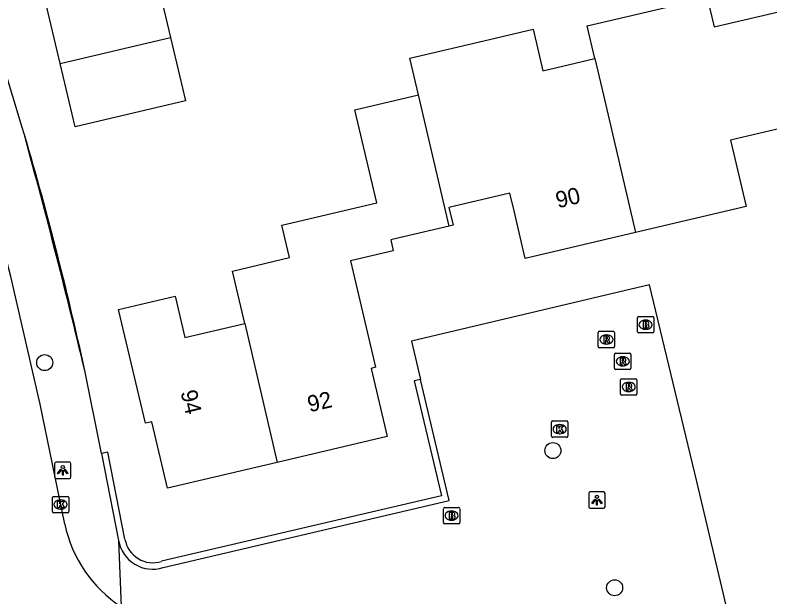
# Model space of a CAD drawing. Extents: x 157663 to 158496, y 379212 to 380934.
# Drawn here: x 158281.55 to 158327.67, y 380607.68 to 380643.22 of the extents above; entities that cross this region are included whole.
import ezdxf

# ---------------------------------------------------------------- set-up
doc = ezdxf.new("R2010")
doc.units = 0
for name, color, linetype in [('IMGEO_Boom', 7, 'Continuous'), ('IMGEO_Brandkraan', 7, 'Continuous'), ('IMGEO_Haag', 7, 'Continuous'), ('IMGEO_Hek', 7, 'Continuous'), ('IMGEO_Kolk', 7, 'Continuous'), ('IMGEO_Lichtpunt', 7, 'Continuous'), ('IMGEO_Pand', 7, 'Continuous'), ('IMGEO_Pand_nummerreeks', 7, 'Continuous'), ('IMGEO_Rijbaan_lokaal_open', 7, 'Continuous'), ('IMGEO_Rioolput', 7, 'Continuous'), ('IMGEO_Voetpad_open', 7, 'Continuous')]:
    doc.layers.add(name, color=color, linetype=linetype)

msp = doc.modelspace()

# ---------------------------------------------------------------- linework, layer by layer
at = {"layer": 'IMGEO_Boom'}
for centre in [(158283.36, 380621.994), (158314.409, 380616.619), (158318.184, 380608.243)]:
    msp.add_circle(centre, 0.489, dxfattribs=at)
at = {"layer": 'IMGEO_Brandkraan'}
for p, q in [((158319.57, 380623.885), (158319.57, 380624.737)), ((158319.645, 380624.811), (158320.497, 380624.811)), ((158320.058, 380624.591), (158320.083, 380624.591)), ((158320.571, 380624.737), (158320.571, 380623.885)), ((158320.081, 380624.031), (158320.056, 380624.031)), ((158320.497, 380623.811), (158319.645, 380623.811)), ((158307.721, 380612.222), (158307.721, 380613.074)), ((158307.796, 380613.148), (158308.648, 380613.148)), ((158308.209, 380612.928), (158308.234, 380612.928)), ((158308.722, 380613.074), (158308.722, 380612.222)), ((158308.648, 380612.148), (158307.796, 380612.148)), ((158308.232, 380612.368), (158308.207, 380612.368))]:
    msp.add_line(p, q, dxfattribs=at)
for points in [[(158319.57, 380623.885), (158319.57, 380624.737)], [(158319.645, 380624.811), (158320.497, 380624.811)], [(158319.918, 380624.511), (158319.918, 380624.111), (158320.131, 380624.111)], [(158320.149, 380624.511), (158319.918, 380624.511)], [(158320.097, 380624.43), (158320.043, 380624.43), (158320.043, 380624.354)], [(158320.571, 380624.737), (158320.571, 380623.885)], [(158320.043, 380624.354), (158320.096, 380624.354)], [(158320.105, 380624.278), (158320.043, 380624.278), (158320.043, 380624.197)], [(158320.043, 380624.197), (158320.105, 380624.197)], [(158320.497, 380623.811), (158319.645, 380623.811)], [(158307.721, 380612.222), (158307.721, 380613.074)], [(158307.796, 380613.148), (158308.648, 380613.148)], [(158308.722, 380613.074), (158308.722, 380612.222)], [(158308.069, 380612.848), (158308.069, 380612.448), (158308.282, 380612.448)], [(158308.3, 380612.848), (158308.069, 380612.848)], [(158308.248, 380612.767), (158308.194, 380612.767), (158308.194, 380612.691)], [(158308.194, 380612.691), (158308.247, 380612.691)], [(158308.256, 380612.615), (158308.194, 380612.615), (158308.194, 380612.534)], [(158308.194, 380612.534), (158308.256, 380612.534)], [(158308.648, 380612.148), (158307.796, 380612.148)]]:
    msp.add_lwpolyline(points, dxfattribs=at)
for centre, radius, start, end in [((158319.647, 380624.735), 0.0765, 91.552, 178.448), ((158319.647, 380624.735), 0.0765, 91.552, 178.448), ((158320.098, 380624.392), 0.0379, 267.8285, 90.9355), ((158320.153, 380624.366), 0.145, 59.4692, 91.5367), ((158320.178, 380624.413), 0.0922, 285.5137, 58.1501), ((158320.495, 380624.735), 0.0765, 1.552, 88.448), ((158320.495, 380624.735), 0.0765, 1.552, 88.448), ((158320.106, 380624.237), 0.0404, 269.8759, 90.5077), ((158320.137, 380624.362), 0.251, 268.6676, 293.5347), ((158320.183, 380624.221), 0.105, 301.3115, 78.989), ((158319.647, 380623.887), 0.0765, 181.552, 268.448), ((158319.647, 380623.887), 0.0765, 181.552, 268.448), ((158320.495, 380623.887), 0.0765, 271.552, 358.448), ((158320.495, 380623.887), 0.0765, 271.552, 358.448), ((158307.798, 380613.072), 0.0765, 91.552, 178.448), ((158307.798, 380613.072), 0.0765, 91.552, 178.448), ((158308.646, 380613.072), 0.0765, 1.552, 88.448), ((158308.646, 380613.072), 0.0765, 1.552, 88.448), ((158308.249, 380612.729), 0.0379, 267.8285, 90.9355), ((158308.257, 380612.574), 0.0404, 269.8759, 90.5077), ((158308.288, 380612.699), 0.251, 268.6676, 293.5347), ((158308.304, 380612.703), 0.145, 59.4692, 91.5367), ((158308.329, 380612.75), 0.0922, 285.5137, 58.1501), ((158308.334, 380612.558), 0.105, 301.3115, 78.989), ((158307.798, 380612.224), 0.0765, 181.552, 268.448), ((158307.798, 380612.224), 0.0765, 181.552, 268.448), ((158308.646, 380612.224), 0.0765, 271.552, 358.448), ((158308.646, 380612.224), 0.0765, 271.552, 358.448)]:
    msp.add_arc(centre, radius, start, end, dxfattribs=at)
for centre, major_axis, ratio, start_param, end_param in [((158320.057, 380624.311), (-0.387, 0.002), 0.722429, 4.712389, 7.853982), ((158320.082, 380624.311), (-0.39, 0.002), 0.717154, 1.570796, 4.712389), ((158308.208, 380612.648), (-0.387, 0.002), 0.722429, 4.712389, 7.853982), ((158308.233, 380612.648), (-0.39, 0.002), 0.717154, 1.570796, 4.712389)]:
    msp.add_ellipse(centre, major_axis=major_axis, ratio=ratio, start_param=start_param, end_param=end_param, dxfattribs=at)
at = {"layer": 'IMGEO_Haag'}
for points in [[(158306.328, 380620.973), (158305.939, 380620.881), (158307.597, 380613.868), (158290.496, 380609.857)], [(158288.265, 380611.201), (158287.219, 380616.53), (158286.826, 380616.453)]]:
    msp.add_lwpolyline(points, dxfattribs=at)
msp.add_arc((158289.966, 380611.5), 1.727, 189.9838, 287.885, dxfattribs=at)
at = {"layer": 'IMGEO_Hek'}
msp.add_arc((157862.374, 380520.498), 435.318, 13.41743, 15.43611, dxfattribs=at)
at = {"layer": 'IMGEO_Kolk'}
for p, q in [((158314.398, 380618.432), (158315.25, 380618.432)), ((158314.323, 380617.506), (158314.323, 380618.358)), ((158314.811, 380618.212), (158314.836, 380618.212)), ((158315.324, 380618.358), (158315.324, 380617.506)), ((158314.834, 380617.652), (158314.809, 380617.652)), ((158315.25, 380617.432), (158314.398, 380617.432)), ((158283.903, 380613.824), (158284.755, 380613.824)), ((158283.828, 380612.898), (158283.828, 380613.75)), ((158284.316, 380613.604), (158284.341, 380613.604)), ((158284.829, 380613.75), (158284.829, 380612.898)), ((158284.339, 380613.044), (158284.314, 380613.044)), ((158284.755, 380612.824), (158283.903, 380612.824))]:
    msp.add_line(p, q, dxfattribs=at)
for points in [[(158314.398, 380618.432), (158315.25, 380618.432)], [(158314.323, 380617.506), (158314.323, 380618.358)], [(158314.644, 380618.132), (158314.767, 380618.132), (158314.767, 380617.981), (158314.897, 380618.132), (158315.061, 380618.132), (158314.915, 380617.981), (158315.068, 380617.732), (158314.916, 380617.732), (158314.831, 380617.896), (158314.767, 380617.829), (158314.767, 380617.732), (158314.644, 380617.732), (158314.644, 380618.132)], [(158315.324, 380618.358), (158315.324, 380617.506)], [(158315.25, 380617.432), (158314.398, 380617.432)], [(158283.903, 380613.824), (158284.755, 380613.824)], [(158283.828, 380612.898), (158283.828, 380613.75)], [(158284.149, 380613.524), (158284.272, 380613.524), (158284.272, 380613.373), (158284.402, 380613.524), (158284.566, 380613.524), (158284.42, 380613.373), (158284.573, 380613.124), (158284.421, 380613.124), (158284.336, 380613.288), (158284.272, 380613.221), (158284.272, 380613.124), (158284.149, 380613.124), (158284.149, 380613.524)], [(158284.829, 380613.75), (158284.829, 380612.898)], [(158284.755, 380612.824), (158283.903, 380612.824)]]:
    msp.add_lwpolyline(points, dxfattribs=at)
for centre, start, end in [((158314.4, 380618.356), 91.552, 178.448), ((158314.4, 380618.356), 91.552, 178.448), ((158315.248, 380618.356), 1.552, 88.448), ((158315.248, 380618.356), 1.552, 88.448), ((158314.4, 380617.508), 181.552, 268.448), ((158314.4, 380617.508), 181.552, 268.448), ((158315.248, 380617.508), 271.552, 358.448), ((158315.248, 380617.508), 271.552, 358.448), ((158283.905, 380613.748), 91.552, 178.448), ((158283.905, 380613.748), 91.552, 178.448), ((158284.753, 380613.748), 1.552, 88.448), ((158284.753, 380613.748), 1.552, 88.448), ((158283.905, 380612.9), 181.552, 268.448), ((158283.905, 380612.9), 181.552, 268.448), ((158284.753, 380612.9), 271.552, 358.448), ((158284.753, 380612.9), 271.552, 358.448)]:
    msp.add_arc(centre, 0.0765, start, end, dxfattribs=at)
for centre, major_axis, ratio, start_param, end_param in [((158314.81, 380617.932), (-0.387, 0.002), 0.722429, 4.712389, 7.853982), ((158314.835, 380617.932), (-0.39, 0.002), 0.717154, 1.570796, 4.712389), ((158284.315, 380613.324), (-0.387, 0.002), 0.722429, 4.712389, 7.853982), ((158284.34, 380613.324), (-0.39, 0.002), 0.717154, 1.570796, 4.712389)]:
    msp.add_ellipse(centre, major_axis=major_axis, ratio=ratio, start_param=start_param, end_param=end_param, dxfattribs=at)
at = {"layer": 'IMGEO_Lichtpunt'}
for p, q in [((158283.965, 380615.82), (158283.965, 380615.013)), ((158283.965, 380615.82), (158283.965, 380615.013)), ((158284.867, 380615.915), (158284.059, 380615.915)), ((158284.867, 380615.915), (158284.059, 380615.915)), ((158284.961, 380615.013), (158284.961, 380615.82)), ((158284.961, 380615.013), (158284.961, 380615.82)), ((158284.059, 380614.919), (158284.867, 380614.919)), ((158284.059, 380614.919), (158284.867, 380614.919)), ((158316.601, 380613.999), (158316.601, 380613.192)), ((158316.601, 380613.999), (158316.601, 380613.192)), ((158317.503, 380614.094), (158316.695, 380614.094)), ((158317.503, 380614.094), (158316.695, 380614.094)), ((158317.597, 380613.192), (158317.597, 380613.999)), ((158317.597, 380613.192), (158317.597, 380613.999)), ((158316.695, 380613.098), (158317.503, 380613.098)), ((158316.695, 380613.098), (158317.503, 380613.098))]:
    msp.add_line(p, q, dxfattribs=at)
for points in [[(158284.339, 380615.484), (158284.378, 380615.456), (158284.19, 380615.194), (158284.152, 380615.221), (158284.339, 380615.484)], [(158284.441, 380615.436), (158284.488, 380615.436), (158284.488, 380615.114), (158284.441, 380615.114), (158284.441, 380615.436)], [(158284.551, 380615.456), (158284.589, 380615.483), (158284.776, 380615.221), (158284.737, 380615.193), (158284.551, 380615.456)], [(158316.975, 380613.663), (158317.014, 380613.635), (158316.826, 380613.373), (158316.788, 380613.4), (158316.975, 380613.663)], [(158317.077, 380613.615), (158317.124, 380613.615), (158317.124, 380613.293), (158317.077, 380613.293), (158317.077, 380613.615)], [(158317.187, 380613.635), (158317.225, 380613.662), (158317.412, 380613.4), (158317.373, 380613.372), (158317.187, 380613.635)]]:
    msp.add_lwpolyline(points, dxfattribs=at)
for centre in [(158284.464, 380615.618), (158317.1, 380613.797)]:
    msp.add_circle(centre, 0.0994, dxfattribs=at)
for centre, start, end in [((158284.059, 380615.82), 90, 180), ((158284.059, 380615.82), 90, 180), ((158284.867, 380615.82), 0, 90), ((158284.867, 380615.82), 0, 90), ((158284.059, 380615.013), 180, 270), ((158284.059, 380615.013), 180, 270), ((158284.867, 380615.013), 270, 0), ((158284.867, 380615.013), 270, 360), ((158316.695, 380613.999), 90, 180), ((158316.695, 380613.999), 90, 180), ((158317.503, 380613.999), 0, 90), ((158317.503, 380613.999), 0, 90), ((158316.695, 380613.192), 180, 270), ((158316.695, 380613.192), 180, 270), ((158317.503, 380613.192), 270, 0), ((158317.503, 380613.192), 270, 360)]:
    msp.add_arc(centre, 0.0946, start, end, dxfattribs=at)
at = {"layer": 'IMGEO_Pand'}
for points in [[(158284.305, 380640.265), (158283.395, 380644.136), (158290.137, 380645.719), (158291.046, 380641.85)], [(158316.97, 380640.574), (158316.5, 380642.576), (158323.841, 380644.3), (158324.263, 380642.505), (158334.831, 380644.988), (158338.49, 380629.41)], [(158306.193, 380638.357), (158305.669, 380640.588), (158310.537, 380641.732), (158313.202, 380642.358), (158313.796, 380639.828), (158316.97, 380640.574)], [(158291.046, 380641.85), (158291.955, 380637.978), (158285.214, 380636.395), (158284.305, 380640.265)], [(158284.305, 380640.265), (158291.046, 380641.85)], [(158316.97, 380640.574), (158317.497, 380638.329), (158319.465, 380629.95)], [(158295.578, 380624.388), (158294.826, 380627.586), (158298.321, 380628.407), (158297.854, 380630.395), (158303.656, 380631.758), (158302.319, 380637.447), (158306.193, 380638.357)], [(158308.08, 380630.334), (158306.193, 380638.357)], [(158331.691, 380627.813), (158330.427, 380627.557), (158330.324, 380627.996), (158331.494, 380628.271), (158330.679, 380631.736), (158329.509, 380631.465), (158328.37, 380636.312), (158325.265, 380635.583), (158326.215, 380631.535), (158319.465, 380629.95)], [(158319.465, 380629.95), (158312.717, 380628.365), (158312.036, 380631.263), (158311.78, 380632.354), (158308.06, 380631.481), (158308.316, 380630.389), (158308.08, 380630.334)], [(158308.08, 380630.334), (158305.278, 380629.676), (158304.499, 380629.493), (158304.658, 380628.818), (158302.051, 380628.206), (158303.577, 380621.71), (158303.307, 380621.646), (158304.286, 380617.478), (158297.573, 380615.901)], [(158297.573, 380615.901), (158290.858, 380614.324), (158289.904, 380618.383), (158289.518, 380618.292), (158287.878, 380625.235), (158291.329, 380626.045), (158291.92, 380623.529), (158295.578, 380624.388)], [(158295.578, 380624.388), (158297.573, 380615.901)]]:
    msp.add_lwpolyline(points, dxfattribs=at)
at = {"layer": 'IMGEO_Rijbaan_lokaal_open'}
msp.add_lwpolyline([(158284.585, 380612.128), (158283.092, 380619.448), (158281.301, 380627.252), (158279.102, 380635.44), (158277.35, 380641.254), (158275.628, 380646.459), (158269.134, 380664.006), (158269.099, 380664.106)], dxfattribs=at)
msp.add_arc((158292.409, 380613.78), 7.996, 191.92, 236.8741, dxfattribs=at)
at = {"layer": 'IMGEO_Rioolput'}
for p, q in [((158317.181, 380622.981), (158317.181, 380623.833)), ((158317.256, 380623.907), (158318.108, 380623.907)), ((158317.669, 380623.687), (158317.694, 380623.687)), ((158318.182, 380623.833), (158318.182, 380622.981)), ((158317.692, 380623.127), (158317.667, 380623.127)), ((158318.108, 380622.907), (158317.256, 380622.907)), ((158318.255, 380622.575), (158319.107, 380622.575)), ((158318.18, 380621.649), (158318.18, 380622.501)), ((158318.668, 380622.355), (158318.693, 380622.355)), ((158319.181, 380622.501), (158319.181, 380621.649)), ((158318.691, 380621.795), (158318.666, 380621.795)), ((158319.107, 380621.575), (158318.255, 380621.575)), ((158318.543, 380620.085), (158318.543, 380620.937)), ((158318.618, 380621.011), (158319.47, 380621.011)), ((158319.031, 380620.791), (158319.056, 380620.791)), ((158319.544, 380620.937), (158319.544, 380620.085)), ((158319.47, 380620.011), (158318.618, 380620.011)), ((158319.054, 380620.231), (158319.029, 380620.231))]:
    msp.add_line(p, q, dxfattribs=at)
for points in [[(158317.181, 380622.981), (158317.181, 380623.833)], [(158317.256, 380623.907), (158318.108, 380623.907)], [(158317.77, 380623.605), (158317.518, 380623.607), (158317.518, 380623.207)], [(158317.696, 380623.526), (158317.642, 380623.526), (158317.642, 380623.445)], [(158318.182, 380623.833), (158318.182, 380622.981)], [(158317.518, 380623.207), (158317.642, 380623.207), (158317.642, 380623.369), (158317.653, 380623.369)], [(158317.642, 380623.445), (158317.694, 380623.445)], [(158317.7, 380623.34), (158317.771, 380623.207), (158317.911, 380623.207), (158317.846, 380623.333)], [(158318.108, 380622.907), (158317.256, 380622.907)], [(158318.255, 380622.575), (158319.107, 380622.575)], [(158318.18, 380621.649), (158318.18, 380622.501)], [(158318.769, 380622.273), (158318.517, 380622.275), (158318.517, 380621.875)], [(158318.695, 380622.194), (158318.641, 380622.194), (158318.641, 380622.113)], [(158318.641, 380622.113), (158318.693, 380622.113)], [(158319.181, 380622.501), (158319.181, 380621.649)], [(158318.517, 380621.875), (158318.641, 380621.875), (158318.641, 380622.037), (158318.652, 380622.037)], [(158318.699, 380622.008), (158318.77, 380621.875), (158318.91, 380621.875), (158318.845, 380622.001)], [(158319.107, 380621.575), (158318.255, 380621.575)], [(158318.543, 380620.085), (158318.543, 380620.937)], [(158318.618, 380621.011), (158319.47, 380621.011)], [(158319.544, 380620.937), (158319.544, 380620.085)], [(158319.132, 380620.709), (158318.88, 380620.711), (158318.88, 380620.311)], [(158318.88, 380620.311), (158319.004, 380620.311), (158319.004, 380620.473), (158319.015, 380620.473)], [(158319.058, 380620.63), (158319.004, 380620.63), (158319.004, 380620.549)], [(158319.004, 380620.549), (158319.056, 380620.549)], [(158319.062, 380620.444), (158319.133, 380620.311), (158319.273, 380620.311), (158319.208, 380620.437)], [(158319.47, 380620.011), (158318.618, 380620.011)]]:
    msp.add_lwpolyline(points, dxfattribs=at)
for centre, radius, start, end in [((158317.258, 380623.831), 0.0765, 91.552, 178.448), ((158317.258, 380623.831), 0.0765, 91.552, 178.448), ((158317.702, 380623.43), 0.0964, 77.0061, 93.1865), ((158317.716, 380623.487), 0.0378, 276.6634, 79.6772), ((158317.769, 380623.495), 0.109, 350.3612, 89.416), ((158318.106, 380623.831), 0.0765, 1.552, 88.448), ((158318.106, 380623.831), 0.0765, 1.552, 88.448), ((158317.652, 380623.316), 0.0533, 26.0293, 88.6989), ((158317.678, 380623.634), 0.19, 274.7715, 282.9687), ((158317.767, 380623.495), 0.112, 277.5842, 350.9817), ((158317.751, 380623.28), 0.108, 29.5134, 73.7905), ((158317.258, 380622.983), 0.0765, 181.552, 268.448), ((158317.258, 380622.983), 0.0765, 181.552, 268.448), ((158318.106, 380622.983), 0.0765, 271.552, 358.448), ((158318.106, 380622.983), 0.0765, 271.552, 358.448), ((158318.257, 380622.499), 0.0765, 91.552, 178.448), ((158318.257, 380622.499), 0.0765, 91.552, 178.448), ((158319.105, 380622.499), 0.0765, 1.552, 88.448), ((158319.105, 380622.499), 0.0765, 1.552, 88.448), ((158318.677, 380622.302), 0.19, 274.7715, 282.9687), ((158318.701, 380622.098), 0.0964, 77.0061, 93.1865), ((158318.715, 380622.155), 0.0378, 276.6634, 79.6772), ((158318.768, 380622.163), 0.109, 350.3612, 89.416), ((158318.766, 380622.163), 0.112, 277.5842, 350.9817), ((158318.651, 380621.984), 0.0533, 26.0293, 88.6989), ((158318.75, 380621.948), 0.108, 29.5134, 73.7905), ((158318.257, 380621.651), 0.0765, 181.552, 268.448), ((158318.257, 380621.651), 0.0765, 181.552, 268.448), ((158319.105, 380621.651), 0.0765, 271.552, 358.448), ((158319.105, 380621.651), 0.0765, 271.552, 358.448), ((158318.62, 380620.935), 0.0765, 91.552, 178.448), ((158318.62, 380620.935), 0.0765, 91.552, 178.448), ((158319.468, 380620.935), 0.0765, 1.552, 88.448), ((158319.468, 380620.935), 0.0765, 1.552, 88.448), ((158319.014, 380620.42), 0.0533, 26.0293, 88.6989), ((158319.04, 380620.738), 0.19, 274.7715, 282.9687), ((158319.064, 380620.534), 0.0964, 77.0061, 93.1865), ((158319.078, 380620.591), 0.0378, 276.6634, 79.6772), ((158319.131, 380620.599), 0.109, 350.3612, 89.416), ((158319.129, 380620.599), 0.112, 277.5842, 350.9817), ((158319.113, 380620.384), 0.108, 29.5134, 73.7905), ((158318.62, 380620.087), 0.0765, 181.552, 268.448), ((158318.62, 380620.087), 0.0765, 181.552, 268.448), ((158319.468, 380620.087), 0.0765, 271.552, 358.448), ((158319.468, 380620.087), 0.0765, 271.552, 358.448)]:
    msp.add_arc(centre, radius, start, end, dxfattribs=at)
for centre, major_axis, ratio, start_param, end_param in [((158317.668, 380623.407), (-0.387, 0.002), 0.722429, 4.712389, 7.853982), ((158317.693, 380623.407), (-0.39, 0.002), 0.717154, 1.570796, 4.712389), ((158318.667, 380622.075), (-0.387, 0.002), 0.722429, 4.712389, 7.853982), ((158318.692, 380622.075), (-0.39, 0.002), 0.717154, 1.570796, 4.712389), ((158319.03, 380620.511), (-0.387, 0.002), 0.722429, 4.712389, 7.853982), ((158319.055, 380620.511), (-0.39, 0.002), 0.717154, 1.570796, 4.712389)]:
    msp.add_ellipse(centre, major_axis=major_axis, ratio=ratio, start_param=start_param, end_param=end_param, dxfattribs=at)
at = {"layer": 'IMGEO_Voetpad_open'}
for points in [[(158281.989, 380636.364), (158280.184, 380642.245), (158278.162, 380648.233), (158274.614, 380657.836), (158272.089, 380664.599)], [(158326.199, 380575.894), (158320.737, 380598.882), (158326.647, 380600.235), (158324.911, 380607.502), (158323.196, 380614.738), (158320.313, 380626.756), (158305.772, 380623.305), (158306.328, 380620.973)], [(158286.826, 380616.453), (158285.81, 380621.511)], [(158290.602, 380609.471), (158308.079, 380613.57), (158306.328, 380620.973)], [(158286.826, 380616.453), (158287.872, 380611.127)], [(158287.872, 380611.127), (158288.039, 380607.083)]]:
    msp.add_lwpolyline(points, dxfattribs=at)
for centre, radius, start, end in [((158084.586, 380577.663), 205.946, 12.29289, 16.56065), ((158289.966, 380611.501), 2.127, 190.1202, 287.3983)]:
    msp.add_arc(centre, radius, start, end, dxfattribs=at)

# ---------------------------------------------------------------- texts
at = {"layer": 'IMGEO_Pand_nummerreeks'}
for s, rotation, p in [('90', 13.2164, (158314.713, 380631.423)), ('94', 283.2902, (158291.656, 380620.202)), ('92', 13.2182, (158299.545, 380618.954))]:
    msp.add_text(s, height=1, rotation=rotation, dxfattribs=at).set_placement(p)

doc.saveas('drawing.dxf')
